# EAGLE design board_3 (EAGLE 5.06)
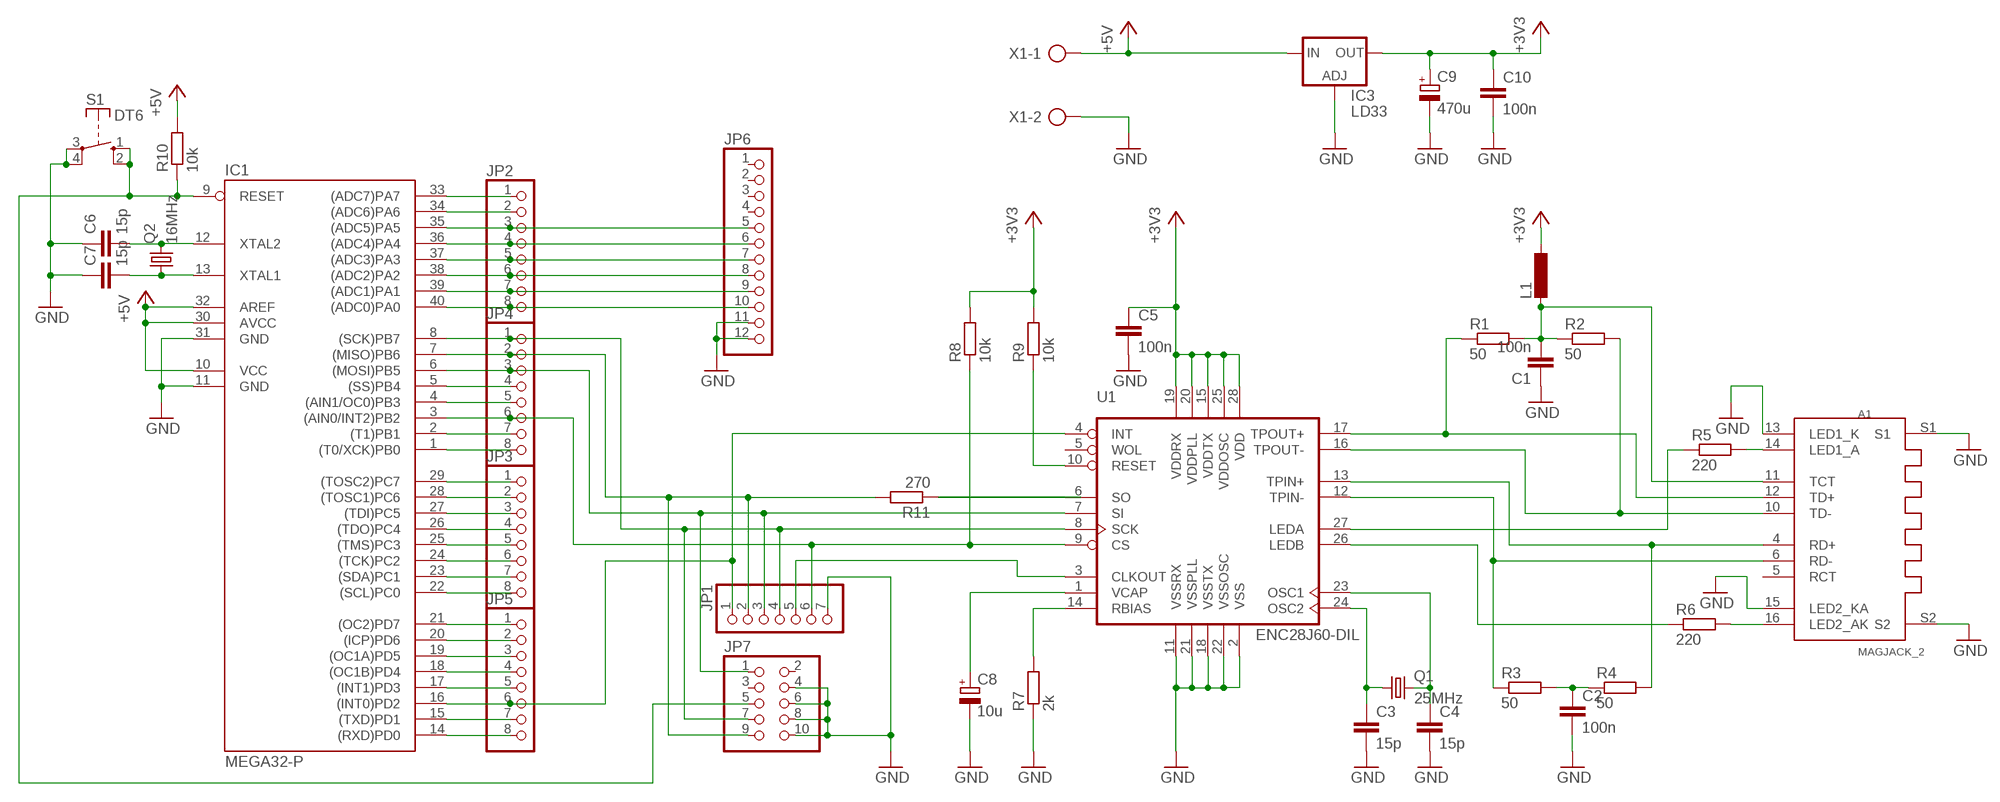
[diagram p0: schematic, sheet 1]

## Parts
A1  MAGJACK_2  [L829-1X1T-91]
C1  100n  C-EU050-045X075  [C050-045X075]
C2  100n  C-EU050-045X075  [C050-045X075]
C3  15p  C-EU050-030X075  [C050-030X075]
C4  15p  C-EU050-030X075  [C050-030X075]
C5  100n  C-EU050-045X075  [C050-045X075]
C6  15p  C-EU050-030X075  [C050-030X075]
C7  15p  C-EU050-030X075  [C050-030X075]
C8  10u  CPOL-EUE2.5-7  [E2,5-7]
C9  470u  CPOL-EUE5-8.5  [E5-8,5]
C10  100n  C-EU075-052X106  [C075-052X106]
IC1  MEGA32-P  [DIL40]
IC3  LD33  LM317TS  [317TS]
JP1  PINHD-1X7  [1X07]
JP2  PINHD-1X8  [1X08]
JP3  PINHD-1X8  [1X08]
JP4  PINHD-1X8  [1X08]
JP5  PINHD-1X8  [1X08]
JP6  PINHD-1X12  [1X12]
JP7  PINHD-2X5  [2X05]
L1  L-EU0207/7  [0207/7]
Q1  25MHz  CRYSTALHC49U-V  [HC49U-V]
Q2  16MHz  CRYSTALHC49U-V  [HC49U-V]
R1  50  R-EU_0207/10  [0207/10]
R2  50  R-EU_0207/10  [0207/10]
R3  50  R-EU_0207/10  [0207/10]
R4  50  R-EU_0207/10  [0207/10]
R5  220  R-EU_0207/10  [0207/10]
R6  220  R-EU_0207/10  [0207/10]
R7  2k  R-EU_0207/10  [0207/10]
R8  10k  R-EU_0207/10  [0207/10]
R9  10k  R-EU_0207/10  [0207/10]
R10  10k  R-EU_0207/10  [0207/10]
R11  270  R-EU_0207/10  [0207/10]
S1  DT6  [DT6]
U1  ENC28J60-DIL  [DIL28-3]
X1  AK300/2  [AK300/2]

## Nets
+3V3: C5.1 C9.+ C10.1 IC3.2(OUT) L1.1 R8.2 R9.2 U1.15(VDDTX) U1.19(VDDRX) U1.20(VDDPLL) U1.25(VDDOSC) U1.28(VDD)
+5V: IC1.10(VCC) IC1.30(AVCC) IC1.32(AREF) IC3.3(IN) R10.2 X1.1
GND: A1.13(LED1_K) A1.15(LED2_KA) A1.S1 A1.S2 C1.1 C2.2 C3.2 C4.2 C5.2 C6.1 C7.1 C8.- C9.- C10.2 IC1.11(GND) IC1.31(GND) IC3.1(ADJ) JP1.7 JP6.11 JP6.12 JP7.4 JP7.6 JP7.8 JP7.10 R7.1 S1.3(P) S1.4(P) U1.2(VSS) U1.11(VSSRX) U1.18(VSSTX) U1.21(VSSPLL) U1.22(VSSOSC) X1.2
N$1: A1.4(RD+) R4.2 U1.13(TPIN+)
N$2: A1.6(RD-) R3.1 U1.12(TPIN-)
N$3: A1.12(TD+) R1.1 U1.17(TPOUT+)
N$4: A1.10(TD-) R2.2 U1.16(TPOUT-)
N$5: R5.1 U1.27(LEDA)
N$6: R6.1 U1.26(LEDB)
N$7: A1.14(LED1_A) R5.2
N$8: A1.16(LED2_AK) R6.2
N$9: A1.11(TCT) C1.2 L1.2 R1.2 R2.1
N$10: C2.1 R3.2 R4.1
N$11: R7.2 U1.14(RBIAS)
N$12: C4.1 Q1.2 U1.23(OSC1)
N$13: C3.1 Q1.1 U1.24(OSC2)
N$14: C8.+ U1.1(VCAP)
N$15: IC1.3((AIN0/INT2)PB2) JP1.6 JP4.6 R8.1 U1.9(CS)
N$16: R9.1 U1.10(RESET)
N$17: C6.2 IC1.12(XTAL2) Q2.2
N$18: C7.2 IC1.13(XTAL1) Q2.1
N$19: JP1.5 U1.3(CLKOUT)
N$20: IC1.8((SCK)PB7) JP1.4 JP4.1 JP7.7 U1.8(SCK)
N$21: IC1.6((MOSI)PB5) JP1.3 JP4.3 JP7.1 U1.7(SI)
N$22: IC1.7((MISO)PB6) JP1.2 JP4.2 JP7.9 R11.2
N$23: IC1.16((INT0)PD2) JP1.1 JP5.6 U1.4(INT)
N$24: R11.1 U1.6(SO)
N$25: IC1.33((ADC7)PA7) JP2.1
N$26: IC1.34((ADC6)PA6) JP2.2
N$27: IC1.35((ADC5)PA5) JP2.3 JP6.5
N$28: IC1.36((ADC4)PA4) JP2.4 JP6.6
N$29: IC1.37((ADC3)PA3) JP2.5 JP6.7
N$30: IC1.38((ADC2)PA2) JP2.6 JP6.8
N$31: IC1.39((ADC1)PA1) JP2.7 JP6.9
N$32: IC1.40((ADC0)PA0) JP2.8 JP6.10
N$33: IC1.5((SS)PB4) JP4.4
N$34: IC1.4((AIN1/OC0)PB3) JP4.5
N$35: IC1.2((T1)PB1) JP4.7
N$36: IC1.1((T0/XCK)PB0) JP4.8
N$37: IC1.29((TOSC2)PC7) JP3.1
N$38: IC1.28((TOSC1)PC6) JP3.2
N$39: IC1.27((TDI)PC5) JP3.3
N$40: IC1.26((TDO)PC4) JP3.4
N$41: IC1.25((TMS)PC3) JP3.5
N$42: IC1.24((TCK)PC2) JP3.6
N$43: IC1.23((SDA)PC1) JP3.7
N$44: IC1.22((SCL)PC0) JP3.8
N$45: IC1.21((OC2)PD7) JP5.1
N$46: IC1.20((ICP)PD6) JP5.2
N$47: IC1.19((OC1A)PD5) JP5.3
N$48: IC1.18((OC1B)PD4) JP5.4
N$49: IC1.17((INT1)PD3) JP5.5
N$50: IC1.15((TXD)PD1) JP5.7
N$51: IC1.14((RXD)PD0) JP5.8
N$52: IC1.9(RESET) JP7.5 R10.1 S1.1(S) S1.2(S)
Unconnected: A1.5(RCT) JP6.1 JP6.2 JP6.3 JP6.4 JP7.2 JP7.3 U1.5(WOL)

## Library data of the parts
A1 = magjack:MAGJACK: Magjack RJ45: 08B0-1X1T-06-F mcgregor@blackmesaeast.com.pl Magjack RJ45: L829-1X1T-91 huszty.gergo@digitaltrip.hu
C1-C7 C10 = rcl:C-EU: CAPACITOR, European symbol
C8 C9 = rcl:CPOL-EU: POLARIZED CAPACITOR, European symbol
IC1 = atmel:MEGA32-P: MICROCONTROLLER 32 Kbytes FLASH 2 Kbytes SRAM 1 Kbytes EEPROM USART 8-channel 10 bit ADC Source: www.atmel.com .. doc2503.pdf
IC3 = v-reg:LM317TS: VOLTAGE REGULATOR
JP1 = pinhead:PINHD-1X7: PIN HEADER
JP2-JP5 = pinhead:PINHD-1X8: PIN HEADER
JP6 = pinhead:PINHD-1X12: PIN HEADER
JP7 = pinhead:PINHD-2X5: PIN HEADER
L1 = rcl:L-EU: INDUCTOR, European symbol
Q1 Q2 = crystal:CRYSTAL: CRYSTAL
R1-R11 = rcl:R-EU_: RESISTOR, European symbol
S1 = switch-misc:DT: ITT SWITCH
U1 = enc28j60centered:ENC28J60-*: Microchip 10Mbit Ethernet controller with SPI interface Improved SOIC28 layout (pads in 0.01 raster, pin1 slightly smaller). Pin 6 (SO) changed from Out (paralleling several Outs gives an error) to OC. Author: Profi from mikrocontroller.net - forum Date: 2006.0827
X1 = con-ptr500:AK300/2: CONNECTOR

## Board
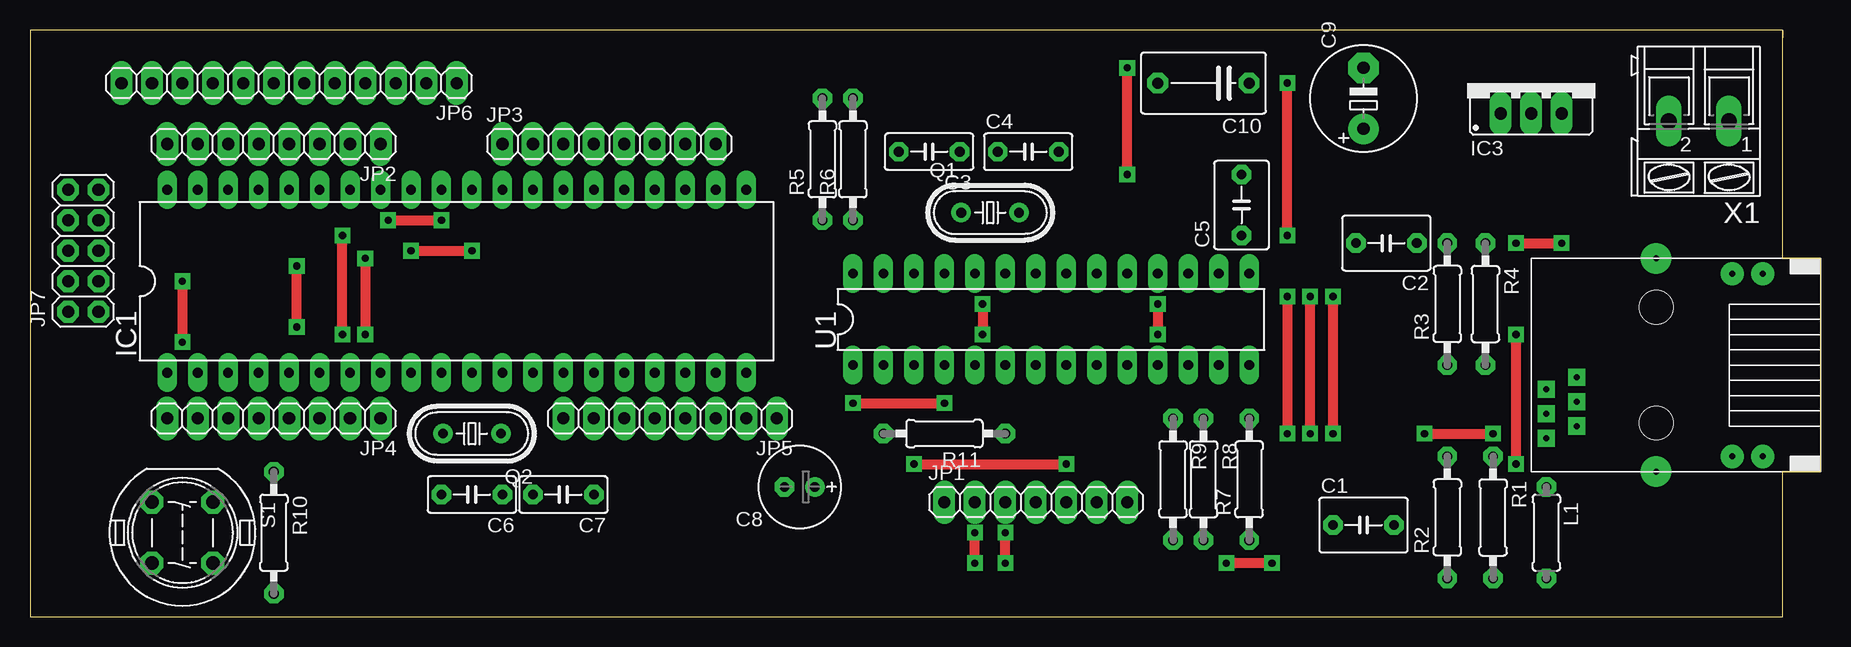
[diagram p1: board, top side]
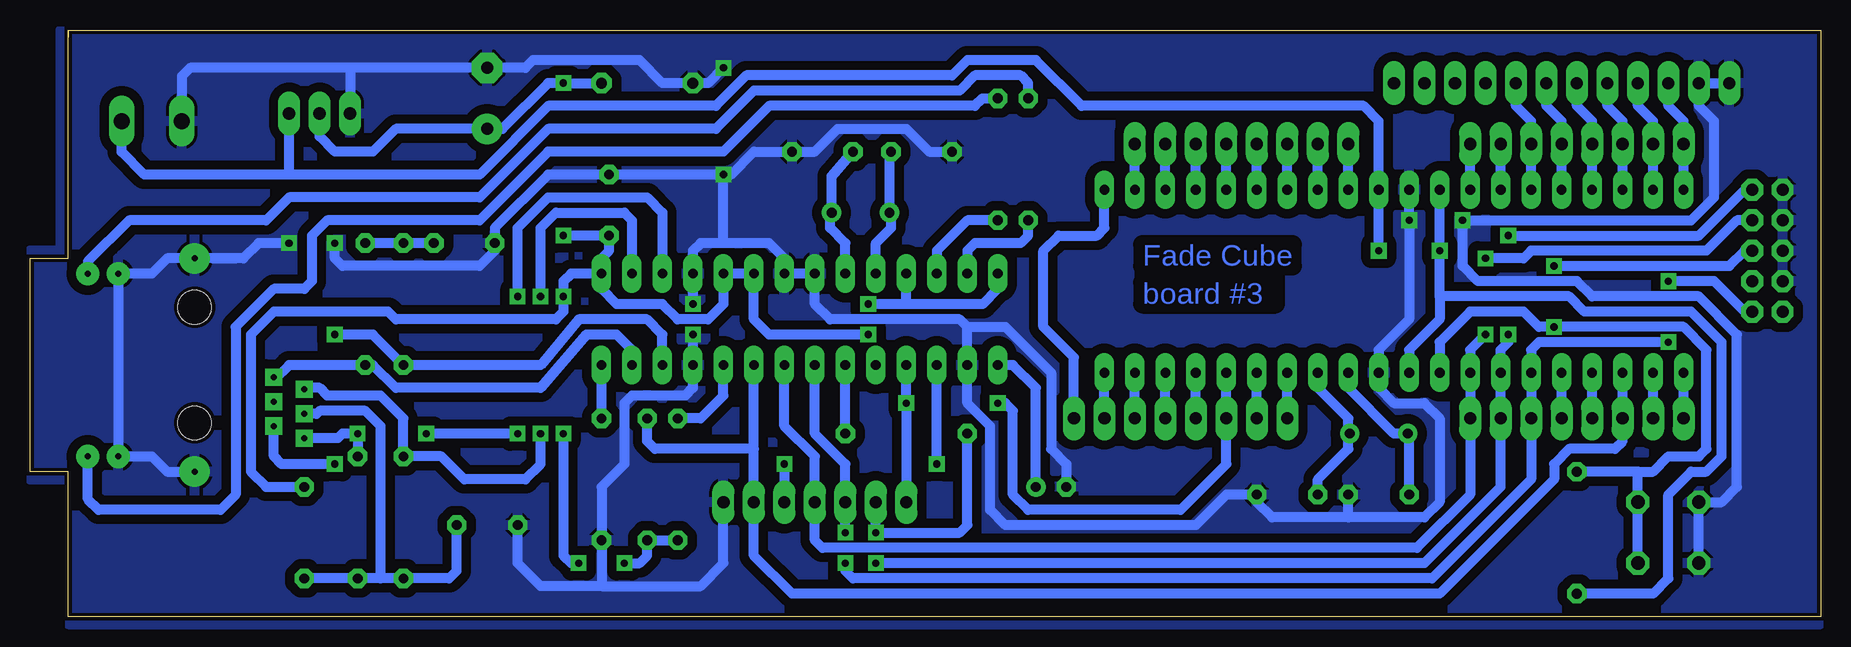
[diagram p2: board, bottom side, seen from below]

Size 149.22 x 48.88 mm. Coordinates in mm from the lower left corner, seen from the top.
Outline: 146.05,48.88 0,48.88 0,0 146.05,0 146.05,12.06 149.22,12.06 149.22,29.84 146.05,29.84 146.05,48.88
Outline: 146.05,48.88 146.05,48.26
Copper layers (1*16): Top 0.035mm / dielectric 1.5mm / Bottom 0.035mm
Design rules "hobby *": minimum track width 0.8mm, minimum drill 0.8mm, track to track 31mil, track to pad 31mil, pad to pad 16mil, via to via 16mil, smd to smd 8mil, copper to edge 12mil, drill to drill 8mil, minimum pad ring 0.4mm, minimum via ring 0.35mm, stop-mask expansion 4mil, vias tented up to drill 0mil, thermal gap 10mil

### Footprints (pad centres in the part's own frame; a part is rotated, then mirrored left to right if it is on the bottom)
L829-1X1T-91 = drill 0.5 pad 1.422 square: 4 9.906,3.81; 5 11.938,3.81; 6 13.97,3.81; 10 10.922,1.27; 11 12.954,1.27; 12 14.986,1.27 | drill 0.5 pad 1.93 round: 13 1.27,16.764; 14 1.27,19.304; 15 16.51,16.764; 16 16.51,19.304 | drill 0.5 pad 2.54 round: S1 0,10.414; S2 17.78,10.414 | hole 2.8: 4.064,10.414; 13.716,10.414
C050-045X075 = drill 0.813 octagon: 1 -2.54,0; 2 2.54,0
C050-030X075 = drill 0.813 octagon: 1 -2.54,0; 2 2.54,0
E2,5-7 = drill 0.813 pad 1.6 round: + -1.27,0 | drill 0.813 pad 1.6 octagon: - 1.27,0
E5-8,5 = drill 1.016 pad 2.54 round: + -2.54,0 | drill 1.016 pad 2.54 octagon: - 2.54,0
C075-052X106 = drill 0.914 octagon: 1 -3.81,0; 2 3.81,0
DIL40 = drill 0.813 long: 1 -24.13,-7.62; 2 -21.59,-7.62; 3 -19.05,-7.62; 4 -16.51,-7.62; 5 -13.97,-7.62; 6 -11.43,-7.62; 7 -8.89,-7.62; 8 -6.35,-7.62; 9 -3.81,-7.62; 10 -1.27,-7.62; 11 1.27,-7.62; 12 3.81,-7.62; 13 6.35,-7.62; 14 8.89,-7.62; 15 11.43,-7.62; 16 13.97,-7.62; 17 16.51,-7.62; 18 19.05,-7.62; 19 21.59,-7.62; 20 24.13,-7.62; 21 24.13,7.62; 22 21.59,7.62; 23 19.05,7.62; 24 16.51,7.62; 25 13.97,7.62; 26 11.43,7.62; 27 8.89,7.62; 28 6.35,7.62; 29 3.81,7.62; 30 1.27,7.62; 31 -1.27,7.62; 32 -3.81,7.62; 33 -6.35,7.62; 34 -8.89,7.62; 35 -11.43,7.62; 36 -13.97,7.62; 37 -16.51,7.62; 38 -19.05,7.62; 39 -21.59,7.62; 40 -24.13,7.62
317TS = drill 1.016 long: 1 -2.54,-2.54; 2 0,-2.54; 3 2.54,-2.54
1X07 = drill 1.016 long: 1 -7.62,0; 2 -5.08,0; 3 -2.54,0; 4 0,0; 5 2.54,0; 6 5.08,0; 7 7.62,0
1X08 = drill 1.016 long: 1 -8.89,0; 2 -6.35,0; 3 -3.81,0; 4 -1.27,0; 5 1.27,0; 6 3.81,0; 7 6.35,0; 8 8.89,0
1X12 = drill 1.016 long: 1 -13.97,0; 2 -11.43,0; 3 -8.89,0; 4 -6.35,0; 5 -3.81,0; 6 -1.27,0; 7 1.27,0; 8 3.81,0; 9 6.35,0; 10 8.89,0; 11 11.43,0; 12 13.97,0
2X05 = drill 1.016 octagon: 1 -5.08,-1.27; 2 -5.08,1.27; 3 -2.54,-1.27; 4 -2.54,1.27; 5 0,-1.27; 6 0,1.27; 7 2.54,-1.27; 8 2.54,1.27; 9 5.08,-1.27; 10 5.08,1.27
0207/7 = drill 0.813 octagon: 1 -3.81,0; 2 3.81,0
HC49U-V = drill 0.813 round: 1 -2.413,0; 2 2.413,0
0207/10 = drill 0.813 octagon: 1 -5.08,0; 2 5.08,0
DT6 = drill 1.118 octagon: 1 -2.54,2.54; 2 2.54,2.54; 3 2.54,-2.54; 4 -2.54,-2.54
DIL28-3 = drill 0.813 long: 1 -16.51,-3.81; 2 -13.97,-3.81; 3 -11.43,-3.81; 4 -8.89,-3.81; 5 -6.35,-3.81; 6 -3.81,-3.81; 7 -1.27,-3.81; 8 1.27,-3.81; 9 3.81,-3.81; 10 6.35,-3.81; 11 8.89,-3.81; 12 11.43,-3.81; 13 13.97,-3.81; 14 16.51,-3.81; 15 16.51,3.81; 16 13.97,3.81; 17 11.43,3.81; 18 8.89,3.81; 19 6.35,3.81; 20 3.81,3.81; 21 1.27,3.81; 22 -1.27,3.81; 23 -3.81,3.81; 24 -6.35,3.81; 25 -8.89,3.81; 26 -11.43,3.81; 27 -13.97,3.81; 28 -16.51,3.81
AK300/2 = drill 1.321 long: 1 -2.515,0; 2 2.489,0

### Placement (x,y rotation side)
A1  125.09,29.84 270 top
C1  111.12,7.62 0 top
C2  113.03,31.11 180 top
C3  74.93,38.73 180 top
C4  83.19,38.73 0 top
C5  100.97,34.29 90 top
C6  36.83,10.16 180 top
C7  44.45,10.16 180 top
C8  64.14,10.79 180 top
C9  111.12,43.18 90 top
C10  97.79,44.45 180 top
IC1  35.56,27.94 0 top
IC3  125.09,44.45 0 top
JP1  83.82,9.53 0 top
JP2  20.32,39.37 180 top
JP3  48.26,39.37 0 top
JP4  20.32,16.51 180 top
JP5  53.34,16.51 180 top
JP6  21.59,44.45 180 top
JP7  4.45,30.48 90 top
L1  126.36,6.99 270 top
Q1  80.01,33.66 0 top
Q2  36.83,15.24 180 top
R1  121.92,8.26 270 top
R2  118.11,8.26 90 top
R3  118.11,26.04 90 top
R4  121.28,26.04 270 top
R5  66.04,38.1 90 top
R6  68.58,38.1 90 top
R7  101.6,11.43 90 top
R8  97.79,11.43 270 top
R9  95.25,11.43 270 top
R10  20.32,6.99 270 top
R11  76.2,15.24 180 top
S1  12.7,6.99 270 top
U1  85.09,24.77 0 top
X1  139.06,41.27 180 top

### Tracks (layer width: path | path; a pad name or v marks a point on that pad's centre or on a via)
+3V3  (via drill 0.6)
  Top 0.813: v79.38,26.04 v79.38,23.5 | v103.5,4.45 v99.69,4.45 | v104.78,26.67 v104.78,15.24 | v104.78,31.75 v104.78,44.45
  Bottom 0.813: U1.15 101.6,27.3 100.33,26.04 96.52,26.04 95.25,24.77 92.71,24.77 91.44,26.04 U1.19 U1.20 88.9,24.77 87.63,23.5 v79.38,23.5 | U1.28 68.58,27.3 69.85,26.04 76.2,26.04 | 76.2,26.04 U1.25 | 76.2,26.04 v79.38,26.04 | U1.15 104.14,28.57 104.78,27.94 v104.78,26.67 104.78,25.4 105.41,24.77 118.75,24.77 119.38,25.4 128.91,25.4 130.81,23.5 130.81,12.06 129.54,10.79 L1.1 | R9.2 R8.2 97.79,5.08 98.42,4.45 v99.69,4.45 | v104.78,31.75 C5.1 100.97,30.48 101.6,29.84 U1.15 | C10.1 v104.78,44.45 106.05,44.45 109.86,40.64 C9.+ 118.75,40.64 120.65,38.73 123.83,38.73 125.09,40.01 IC3.2 | v103.5,4.45 104.14,4.45 104.78,5.08 v104.78,15.24
+5V  (via drill 0.6)
  Top 0.813: v31.75,30.48 v36.83,30.48
  Bottom 0.813: IC1.10 34.29,22.23 31.75,24.77 31.75,26.67 | IC1.32 v31.75,30.48 31.75,26.67 | v36.83,30.48 IC1.30 36.83,41.27 38.1,42.55 61.59,42.55 65.41,46.35 71.12,46.35 72.39,45.09 89.53,45.09 92.08,42.55 106.05,42.55 111.76,36.83 127.64,36.83 | R10.2 13.97,1.91 12.7,3.17 12.7,10.16 10.79,12.06 9.53,12.06 8.26,13.34 8.26,22.86 10.79,25.4 19.68,25.4 20.95,26.67 31.75,26.67 | X1.1 141.58,38.71 139.7,36.83 127.64,36.83 | 127.64,36.83 IC3.3
GND  (via drill 0.6)
  Top 0.813: v93.98,26.04 v93.98,23.5 | v123.83,31.11 v127.64,31.11 | v91.44,36.83 v91.44,45.72 | v29.84,33.02 v34.29,33.02
  Bottom 0.813: JP6.12 JP6.11 10.16,42.55 8.89,41.27 8.89,34.92 10.79,33.02 v29.84,33.02 29.84,29.21 28.57,27.94 20.32,27.94 19.05,26.67 10.16,26.67 6.99,23.5 6.99,10.79 8.26,9.53 S1.4 S1.3 | 101.6,2.54 R7.1 101.6,10.79 99.69,12.7 99.69,17.78 99.06,18.41 94.61,18.41 93.98,19.05 U1.11 v93.98,23.5 | v93.98,26.04 U1.18 93.98,30.48 93.34,31.11 91.44,31.11 | 91.44,31.11 87.63,31.11 86.36,29.84 U1.21 U1.22 83.82,26.04 82.55,24.77 71.75,24.77 71.12,24.13 | 71.12,24.13 U1.2 71.12,17.78 69.22,15.88 69.22,8.89 67.94,7.62 52.07,7.62 49.53,10.16 C7.1 46.99,9.53 45.72,8.26 39.37,8.26 | A1.S2 137.79,12.06 139.06,13.34 A1.15 A1.13 139.06,28.57 137.79,29.84 A1.S1 133.99,29.84 | v91.44,36.83 C5.2 106.05,36.83 110.49,32.38 C2.2 110.49,30.48 111.76,29.21 123.19,29.21 123.83,29.84 v123.83,31.11 | 133.99,29.84 132.08,29.84 | 133.99,29.84 131.44,29.84 130.18,31.11 v127.64,31.11 | 39.37,8.26 33.02,8.26 31.75,9.53 31.75,16.51 33.02,17.78 35.56,17.78 36.83,19.05 IC1.11 36.83,22.23 34.29,24.77 v34.29,33.02 IC1.31 | 39.37,8.26 C6.1 | 101.6,2.54 93.34,2.54 91.44,4.45 JP1.7 | v91.44,36.83 90.81,36.83 88.9,38.73 C4.2 83.82,38.73 81.92,40.64 76.2,40.64 74.3,38.73 C3.2 | X1.2 136.58,45.03 135.89,45.72 122.56,45.72 | 91.44,31.11 v91.44,36.83 | 122.56,45.72 C9.- 107.95,45.72 107.31,46.35 98.42,46.35 96.52,44.45 C10.2 92.71,44.45 v91.44,45.72 | 122.56,45.72 IC3.1 | 101.6,2.54 106.68,2.54 108.58,4.45 C1.1 | C8.- 62.87,12.7 64.14,13.97 64.14,20.32 67.94,24.13 71.12,24.13
  pour Bottom: 0,48.9 146.69,48.9 146.69,30.48 149.22,30.48 149.22,11.43 146.05,11.43 146.05,-0.64 0,-0.64
N$1
  Bottom 0.813: A1.4 128.91,19.68 127.64,20.95 R4.2 120.65,20.95 118.75,19.05 106.68,19.05 102.87,23.5 100.33,23.5 99.06,22.23 U1.13
N$2  (via drill 0.6)
  Top 0.813: v123.83,23.5 v123.83,12.7
  Bottom 0.813: U1.12 96.52,23.5 97.79,24.77 103.5,24.77 106.68,20.95 R3.1 120.65,23.5 v123.83,23.5 | A1.6 128.91,13.34 128.27,12.7 v123.83,12.7
N$3  (via drill 0.6)
  Top 0.813: v108.58,15.24 v108.58,26.67 | v116.2,15.24 v121.92,15.24
  Bottom 0.813: U1.17 96.52,33.66 97.79,34.92 106.05,34.92 108.58,32.38 v108.58,26.67 | R1.1 v121.92,15.24 123.19,15.24 123.57,14.86 A1.12 | v108.58,15.24 v116.2,15.24
N$4  (via drill 0.6)
  Top 0.813: v106.68,15.24 v106.68,26.67
  Bottom 0.813: U1.16 99.06,33.02 99.69,33.66 105.41,33.66 106.68,32.38 v106.68,26.67 | v106.68,15.24 106.68,12.7 107.95,11.43 113.03,11.43 114.94,13.34 R2.2 118.11,16.51 120.02,18.41 124.46,18.41 125.09,19.05 126.24,19.05 A1.10
N$5
  Bottom 0.813: U1.27 71.12,30.48 70.48,31.11 66.67,31.11 66.04,31.75 R5.1
N$6
  Bottom 0.813: U1.26 73.66,30.48 71.12,33.02 R6.1
N$7
  Bottom 0.813: A1.14 144.4,29.59 140.97,33.02 129.54,33.02 127.64,34.92 111.76,34.92 106.05,40.64 92.08,40.64 88.9,43.81 71.75,43.81 70.48,45.09 66.67,45.09 66.04,44.45 R5.2
N$8
  Bottom 0.813: A1.16 144.4,9.78 143.51,8.89 133.35,8.89 132.08,10.16 132.08,24.13 128.91,27.3 126.36,27.3 125.73,27.94 125.73,31.75 124.46,33.02 111.76,33.02 106.05,38.73 91.44,38.73 87.63,42.55 70.48,42.55 69.85,43.18 R6.2
N$9
  Bottom 0.813: 120.02,3.17 R1.2 L1.2 | 120.02,3.17 R2.1 114.3,3.17 113.67,3.81 C1.2 | 120.02,3.17 120.02,15.88 121.28,17.14 125.09,17.14 125.35,16.89 A1.11
N$10
  Bottom 0.813: R4.1 R3.2 C2.1
N$11
  Bottom 0.813: R7.2 U1.14
N$12
  Bottom 0.813: U1.23 81.28,31.11 82.55,32.38 82.55,33.53 Q1.2 82.42,36.7 C4.1
N$13
  Bottom 0.813: U1.24 78.74,31.11 77.47,32.38 77.47,33.53 Q1.1 77.6,38.61 C3.1
N$14
  Bottom 0.813: U1.1 67.31,20.95 65.41,19.05 C8.+
N$15
  Bottom 0.813: IC1.3 JP4.6 16.51,14.61 17.14,13.97 20.95,13.97 22.23,12.7 22.23,11.43 31.75,1.91 85.72,1.91 88.9,5.08 JP1.6 88.9,13.97 | R8.1 97.79,14.61 97.16,13.97 88.9,13.97 | 88.9,13.97 U1.9
N$16
  Bottom 0.813: R9.1 93.34,16.51 91.44,18.41 U1.10
N$17
  Bottom 0.813: C6.2 34.29,15.11 Q2.2 35.56,15.24 39.37,19.05 IC1.12
N$18
  Bottom 0.813: IC1.13 41.91,19.05 39.37,16.51 39.37,15.37 Q2.1 39.37,15.11 39.37,13.97 41.91,11.43 C7.2
N$19  (via drill 0.6)
  Top 0.813: v73.66,12.7 v86.36,12.7
  Bottom 0.813: v86.36,12.7 JP1.5 | v73.66,12.7 U1.3
N$20  (via drill 0.6)
  Top 0.813: v27.94,29.84 v27.94,23.5
  Bottom 0.813: U1.8 86.36,15.88 83.82,13.34 JP1.4 83.82,6.35 83.19,5.71 33.66,5.71 29.21,10.16 JP4.1 IC1.8 29.21,22.23 v27.94,23.5 | v27.94,29.84 24.77,29.84 24.13,30.48 9.53,30.48 6.99,33.02 JP7.7
N$21  (via drill 0.6)
  Top 0.813: v81.28,4.45 v81.28,6.99 | v12.7,27.94 v12.7,22.86
  Bottom 0.813: 24.13,17.14 JP4.3 | 24.13,17.14 IC1.6 24.13,22.23 23.5,22.86 v12.7,22.86 | U1.7 83.82,15.24 81.28,12.7 JP1.3 v81.28,6.99 | v81.28,4.45 81.28,3.81 80.64,3.17 32.38,3.17 24.13,11.43 24.13,17.14 | JP7.1 6.35,25.4 8.89,27.94 v12.7,27.94
N$22  (via drill 0.6)
  Top 0.813: v78.74,4.45 v78.74,6.99 | v26.04,23.5 v26.04,31.75
  Bottom 0.813: JP1.2 v78.74,6.99 71.75,6.99 71.12,7.62 R11.2 | v78.74,4.45 33.02,4.45 26.67,10.79 JP4.2 IC1.7 26.67,22.23 26.04,22.86 v26.04,23.5 | v26.04,31.75 10.16,31.75 6.35,35.56 JP7.9
N$23  (via drill 0.6)
  Top 0.813: v68.58,17.78 v76.2,17.78
  Bottom 0.813: IC1.16 JP5.6 49.53,12.7 53.34,8.89 66.04,8.89 67.31,10.16 67.31,17.14 67.94,17.78 v68.58,17.78 | JP1.1 v76.2,17.78 U1.4
N$24
  Bottom 0.813: R11.1 U1.6
N$25
  Bottom 0.813: IC1.33 JP2.1
N$26
  Bottom 0.813: IC1.34 JP2.2
N$27
  Bottom 0.813: IC1.35 JP2.3 24.13,41.27 25.4,42.55 JP6.5
N$28
  Bottom 0.813: IC1.36 JP2.4 21.59,41.27 22.86,42.55 JP6.6
N$29
  Bottom 0.813: IC1.37 JP2.5 19.05,41.27 20.32,42.55 JP6.7
N$30
  Bottom 0.813: IC1.38 JP2.6 16.51,41.27 17.78,42.55 JP6.8
N$31
  Bottom 0.813: IC1.39 JP2.7 13.97,41.27 15.24,42.55 JP6.9
N$32
  Bottom 0.813: IC1.40 JP2.8 11.43,41.27 12.7,42.55 JP6.10
N$33
  Bottom 0.813: JP4.4 IC1.5
N$34
  Bottom 0.813: JP4.5 IC1.4
N$35
  Bottom 0.813: JP4.7 IC1.2
N$36
  Bottom 0.813: JP4.8 IC1.1
N$37
  Bottom 0.813: IC1.29 JP3.1
N$38
  Bottom 0.813: IC1.28 JP3.2
N$39
  Bottom 0.813: IC1.27 JP3.3
N$40
  Bottom 0.813: IC1.26 JP3.4
N$41
  Bottom 0.813: IC1.25 JP3.5
N$42
  Bottom 0.813: IC1.24 JP3.6
N$43
  Bottom 0.813: IC1.23 JP3.7
N$44
  Bottom 0.813: IC1.22 JP3.8
N$45
  Bottom 0.813: JP5.1 62.23,21.59 64.77,24.13 64.77,30.48 63.5,31.75 60.33,31.75 59.69,32.38 IC1.21
N$46
  Bottom 0.813: JP5.2 IC1.20
N$47
  Bottom 0.813: JP5.3 IC1.19
N$48
  Bottom 0.813: JP5.4 IC1.18
N$49
  Bottom 0.813: JP5.5 IC1.17
N$50
  Bottom 0.813: JP5.7 IC1.15
N$51
  Bottom 0.813: JP5.8 IC1.14
N$52  (via drill 0.6)
  Top 0.813: v22.23,24.13 v22.23,29.21
  Bottom 0.813: S1.2 S1.1 15.24,12.06 | IC1.9 31.75,22.86 29.21,25.4 24.77,25.4 23.5,24.13 v22.23,24.13 11.43,24.13 9.53,22.23 9.53,13.97 10.16,13.34 12.7,13.34 13.97,12.06 15.24,12.06 | 15.24,12.06 R10.1 | JP7.5 6.35,30.48 7.62,29.21 v22.23,29.21

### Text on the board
Bottom: Fade Cube | board #3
